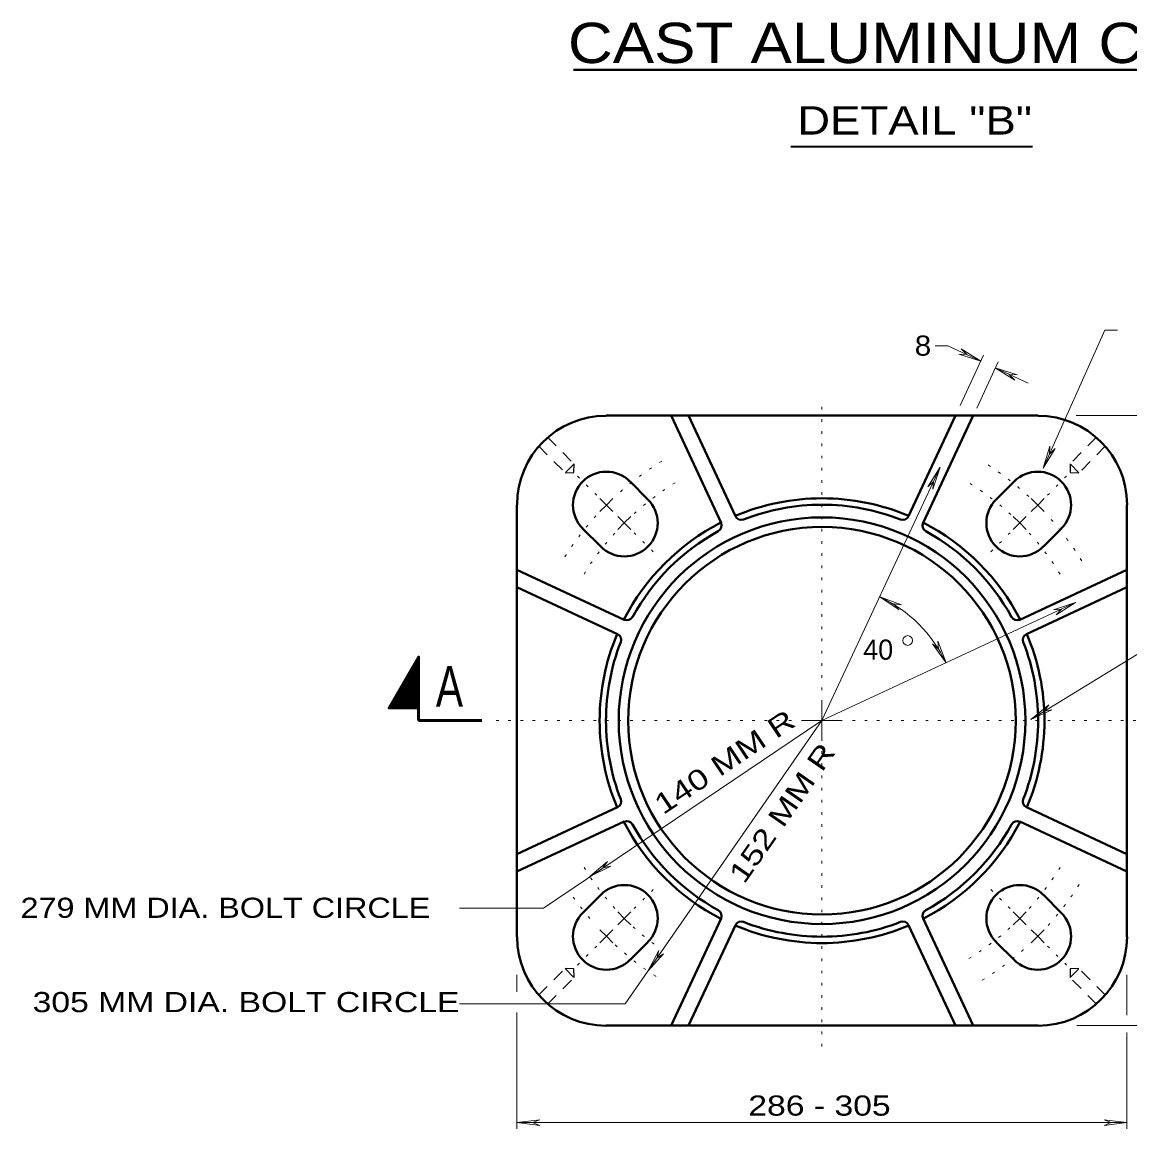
# Model space of a CAD drawing. Extents: x 312583 to 312854, y 144419 to 144597.
# Drawn here: x 312694.63 to 312736.4, y 144504.87 to 144546.6 of the extents above; entities that cross this region are included whole.
import ezdxf
from ezdxf.enums import TextEntityAlignment as Align

# ---------------------------------------------------------------- set-up
doc = ezdxf.new("R2010")
doc.units = 0
doc.header["$LTSCALE"] = 0.3
doc.linetypes.add('DOTTED', pattern=[1.5, 0.3, -1.2])
doc.linetypes.add('SHORT_DASHED', pattern=[2.7, 1.5, -1.2])
doc.layers.add('1', color=7, linetype='Continuous', lineweight=40)
doc.layers.add('2', color=7, linetype='Continuous', lineweight=13)

msp = doc.modelspace()

# ---------------------------------------------------------------- linework, layer by layer
at = {"layer": '1'}
for p, q in [((312724.7891, 144531.7639), (312716.6471, 144531.7639)), ((312720.9864, 144527.7159), (312719.1004, 144531.7639)), ((312721.5307, 144527.9689), (312719.7597, 144531.7639)), ((312732.9387, 144531.7639), (312724.7891, 144531.7639)), ((312728.0551, 144527.9689), (312729.8261, 144531.7639)), ((312728.5994, 144527.7159), (312730.4854, 144531.7639)), ((312717.5517, 144529.2799), (312718.2264, 144528.6052)), ((312731.3594, 144528.6052), (312732.0341, 144529.2799)), ((312713.2891, 144528.4059), (312713.2891, 144520.2639)), ((312736.2891, 144520.2639), (312736.2891, 144528.4059)), ((312716.4477, 144526.8265), (312715.7731, 144527.5012)), ((312733.8127, 144527.5012), (312733.1381, 144526.8265)), ((312717.3371, 144524.0665), (312713.2891, 144525.9525)), ((312732.2487, 144524.0665), (312736.2891, 144525.9525)), ((312717.0841, 144523.5222), (312713.2891, 144525.2932)), ((312732.5017, 144523.5222), (312736.2891, 144525.2932)), ((312713.2891, 144520.2639), (312713.2891, 144512.1142)), ((312736.2891, 144512.1142), (312736.2891, 144520.2639)), ((312717.0841, 144516.9979), (312713.2891, 144515.2269)), ((312732.5017, 144516.9979), (312736.2891, 144515.2269)), ((312717.3371, 144516.4535), (312713.2891, 144514.5675)), ((312732.2487, 144516.4535), (312736.2891, 144514.5675)), ((312715.7731, 144513.0189), (312716.4477, 144513.6935)), ((312733.1381, 144513.6935), (312733.8127, 144513.0189)), ((312720.9864, 144512.8042), (312719.1004, 144508.7639)), ((312728.5994, 144512.8042), (312730.4854, 144508.7639)), ((312721.5307, 144512.5512), (312719.7597, 144508.7639)), ((312728.0551, 144512.5512), (312729.8261, 144508.7639)), ((312718.2264, 144511.9149), (312717.5517, 144511.2402)), ((312732.0341, 144511.2402), (312731.3594, 144511.9149)), ((312716.6471, 144508.7639), (312724.7891, 144508.7639)), ((312724.7891, 144508.7639), (312732.9387, 144508.7639))]:
    msp.add_line(p, q, dxfattribs=at)
at = {"layer": '1', "linetype": 'SHORT_DASHED', "lineweight": 25}
for p, q in [((312714.4467, 144530.9435), (312715.4434, 144529.9469)), ((312735.1314, 144530.9435), (312734.1424, 144529.9469)), ((312714.1094, 144530.6062), (312715.1061, 144529.6095)), ((312735.4687, 144530.6062), (312734.4797, 144529.6095)), ((312714.1094, 144509.9215), (312715.1061, 144510.9105)), ((312735.4687, 144509.9215), (312734.4797, 144510.9105)), ((312714.4467, 144509.5842), (312715.4434, 144510.5732)), ((312735.1314, 144509.5842), (312734.1424, 144510.5732))]:
    msp.add_line(p, q, dxfattribs=at)
for points in [[(312715.4434, 144529.9469), (312715.1061, 144529.6095), (312715.4357, 144529.6172)], [(312734.4797, 144529.6095), (312734.1424, 144529.9469), (312734.1501, 144529.6172)], [(312715.1061, 144510.9105), (312715.4434, 144510.5732), (312715.4357, 144510.9029)], [(312734.1424, 144510.5732), (312734.4797, 144510.9105), (312734.1501, 144510.9029)]]:
    msp.add_lwpolyline(points, close=True, dxfattribs=at)
at = {"layer": '1'}
for centre, radius, start, end in [((312716.6451, 144528.4059), 3.3542, 90, 180), ((312732.9368, 144528.4059), 3.3542, 0, 90), ((312716.6586, 144528.3924), 1.2578, 45, 225), ((312732.9234, 144528.3924), 1.2578, 315, 135), ((312724.791, 144520.26), 8.3854, 90, 112.94673), ((312724.791, 144520.26), 8.3854, 67.05327, 90), ((312717.3371, 144527.714), 1.2578, 225, 45), ((312724.791, 144520.26), 8.1458, 90, 111.30566), ((312724.791, 144520.26), 8.1458, 68.69434, 90), ((312732.2449, 144527.714), 1.2578, 135, 315), ((312724.791, 144520.26), 7.6667, 90, 180), ((312721.744, 144528.0723), 0.2396, 205.00333, 291.30722), ((312724.791, 144520.26), 7.6667, 0, 90), ((312727.838, 144528.0723), 0.2396, 248.69278, 334.99667), ((312724.791, 144520.26), 8.3854, 117.05705, 152.95096), ((312724.791, 144520.26), 7.3073, 90, 180), ((312724.791, 144520.26), 8.1458, 118.68793, 151.31207), ((312720.7656, 144527.6161), 0.2396, 298.68804, 25.01264), ((312724.791, 144520.26), 7.3073, 0, 90), ((312728.8163, 144527.6161), 0.2396, 154.98736, 241.31196), ((312724.791, 144520.26), 8.3854, 27.05705, 62.95096), ((312724.791, 144520.26), 8.1458, 28.68793, 61.31207), ((312717.4349, 144524.2854), 0.2396, 244.98736, 331.31196), ((312732.1471, 144524.2854), 0.2396, 208.68804, 295.01264), ((312724.791, 144520.26), 8.3854, 157.05327, 180), ((312724.791, 144520.26), 8.1458, 158.69434, 180), ((312716.9787, 144523.307), 0.2396, 338.69278, 64.99667), ((312732.6032, 144523.307), 0.2396, 115.00333, 201.30722), ((312724.791, 144520.26), 8.1458, 0, 21.30566), ((312724.791, 144520.26), 8.3854, 0, 22.94673), ((312724.791, 144520.26), 8.3854, 180, 202.94673), ((312724.791, 144520.26), 8.1458, 180, 201.30566), ((312724.791, 144520.26), 7.6667, 180, 270), ((312724.791, 144520.26), 7.3073, 180, 270), ((312724.791, 144520.26), 7.6667, 270, 0), ((312724.791, 144520.26), 7.3073, 270, 0), ((312724.791, 144520.26), 8.1458, 338.69434, 0), ((312724.791, 144520.26), 8.3854, 337.05327, 0), ((312716.9787, 144517.213), 0.2396, 295.00333, 21.30722), ((312732.6032, 144517.213), 0.2396, 158.69278, 244.99667), ((312724.791, 144520.26), 8.3854, 207.05705, 242.95096), ((312717.4349, 144516.2347), 0.2396, 28.68804, 115.01264), ((312724.791, 144520.26), 8.1458, 208.68793, 241.31207), ((312724.791, 144520.26), 8.3854, 297.05705, 332.95096), ((312724.791, 144520.26), 8.1458, 298.68793, 331.31207), ((312732.1471, 144516.2347), 0.2396, 64.98736, 151.31196), ((312717.3371, 144512.8061), 1.2578, 315, 135), ((312732.2449, 144512.8061), 1.2578, 45, 225), ((312716.6586, 144512.1276), 1.2578, 135, 315), ((312720.7656, 144512.904), 0.2396, 334.98736, 61.31196), ((312728.8163, 144512.904), 0.2396, 118.68804, 205.01264), ((312732.9234, 144512.1276), 1.2578, 225, 45), ((312724.791, 144520.26), 8.3854, 247.05327, 270), ((312721.744, 144512.4478), 0.2396, 68.69278, 154.99667), ((312724.791, 144520.26), 8.1458, 248.69434, 270), ((312724.791, 144520.26), 8.1458, 270, 291.30566), ((312724.791, 144520.26), 8.3854, 270, 292.94673), ((312727.838, 144512.4478), 0.2396, 25.00333, 111.30722), ((312716.6451, 144512.1142), 3.3542, 180, 270), ((312732.9368, 144512.1142), 3.3542, 270, 0)]:
    msp.add_arc(centre, radius, start, end, dxfattribs=at)
at = {"layer": '1', "linetype": 'DOTTED', "lineweight": 13}
for radius, start, end in [(11.5, 121.67302, 132.67646), (11.5, 47.32354, 58.32698), (10.5417, 121.67021, 132.50277), (10.5417, 47.49723, 58.32979), (11.5, 137.83702, 148.35019), (11.5, 31.64981, 42.16298), (10.5417, 137.83921, 148.35431), (10.5417, 31.64569, 42.16079), (10.5417, 211.64569, 222.16079), (10.5417, 317.83921, 328.35431), (11.5, 317.83702, 328.35019), (11.5, 215.3347, 222.16255), (10.5417, 227.49787, 233.37708), (10.5417, 301.67021, 312.50277), (11.5, 227.32354, 238.32698), (11.5, 301.67302, 312.67646)]:
    msp.add_arc((312724.791, 144520.26), radius, start, end, dxfattribs=at)
at = {"layer": '2', "lineweight": 40}
msp.add_line((312715.4253, 144544.8043), (312740.0175, 144544.8043), dxfattribs=at)
at = {"layer": '2', "lineweight": 35}
for p, q in [((312723.6187, 144541.9064), (312732.7269, 144541.9064)), ((312709.5784, 144522.2495), (312709.4021, 144522.3492)), ((312709.5784, 144522.2802), (312709.4097, 144522.3722)), ((312709.5784, 144522.3109), (312709.4251, 144522.3952)), ((312709.5784, 144522.3339), (312709.4404, 144522.4105)), ((312709.5784, 144522.3645), (312709.4481, 144522.4335)), ((312709.5784, 144522.3875), (312709.4634, 144522.4565)), ((312709.5784, 144522.4105), (312709.4711, 144522.4795)), ((312709.5784, 144522.4412), (312709.4864, 144522.4949)), ((312709.5784, 144522.4719), (312709.4941, 144522.5179)), ((312709.5784, 144522.5025), (312709.5094, 144522.5409)), ((312709.5784, 144522.5255), (312709.5171, 144522.5562)), ((312709.5784, 144522.5562), (312709.5324, 144522.5792)), ((312709.5784, 144522.5792), (312709.5401, 144522.6022)), ((312709.5784, 144522.6099), (312709.5554, 144522.6175)), ((312709.5784, 144522.6405), (312709.5631, 144522.6405)), ((312709.5784, 144521.6975), (312709.1567, 144521.9352)), ((312709.5784, 144521.7205), (312709.1721, 144521.9582)), ((312709.5784, 144521.7512), (312709.1797, 144521.9812)), ((312709.5784, 144521.7819), (312709.1951, 144521.9965)), ((312709.5784, 144521.8125), (312709.2104, 144522.0195)), ((312709.5784, 144521.8355), (312709.2181, 144522.0425)), ((312709.5784, 144521.8662), (312709.2334, 144522.0579)), ((312709.5784, 144521.8892), (312709.2487, 144522.0809)), ((312709.5784, 144521.9199), (312709.2564, 144522.1039)), ((312709.5784, 144521.9429), (312709.2717, 144522.1192)), ((312709.5784, 144521.9735), (312709.2794, 144522.1422)), ((312709.5784, 144522.0042), (312709.2947, 144522.1652)), ((312709.5784, 144522.0272), (312709.3024, 144522.1805)), ((312709.5784, 144522.0579), (312709.3177, 144522.2112)), ((312709.5784, 144522.0809), (312709.3254, 144522.2265)), ((312709.5784, 144522.1115), (312709.3407, 144522.2495)), ((312709.5784, 144522.1422), (312709.3484, 144522.2725)), ((312709.5784, 144522.1652), (312709.3637, 144522.2879)), ((312709.5784, 144522.1959), (312709.3714, 144522.3109)), ((312709.5784, 144522.2189), (312709.3867, 144522.3339)), ((312709.5707, 144521.1455), (312708.9267, 144521.5212)), ((312709.5784, 144521.1762), (312708.9344, 144521.5442)), ((312709.5784, 144521.1992), (312708.9497, 144521.5595)), ((312709.5784, 144521.2222), (312708.9574, 144521.5825)), ((312709.5784, 144521.2529), (312708.9727, 144521.6055)), ((312709.5784, 144521.2835), (312708.9804, 144521.6209)), ((312709.5784, 144521.3142), (312708.9957, 144521.6439)), ((312709.5784, 144521.3372), (312709.0034, 144521.6669)), ((312709.5784, 144521.3679), (312709.0187, 144521.6822)), ((312709.5707, 144521.3909), (312709.0264, 144521.7129)), ((312709.5784, 144521.4215), (312709.0417, 144521.7282)), ((312709.5784, 144521.4445), (312709.0571, 144521.7512)), ((312709.5784, 144521.4752), (312709.0647, 144521.7742)), ((312709.5784, 144521.5059), (312709.0801, 144521.7895)), ((312709.5784, 144521.5289), (312709.0877, 144521.8125)), ((312709.5784, 144521.5595), (312709.1031, 144521.8355)), ((312709.5784, 144521.5902), (312709.1107, 144521.8509)), ((312709.5784, 144521.6132), (312709.1261, 144521.8739)), ((312709.5784, 144521.6439), (312709.1337, 144521.8969)), ((312709.5784, 144521.6745), (312709.1491, 144521.9122)), ((312709.3177, 144520.7392), (312708.6814, 144521.1072)), ((312709.3637, 144520.7392), (312708.6967, 144521.1225)), ((312709.4097, 144520.7392), (312708.7121, 144521.1455)), ((312709.4634, 144520.7392), (312708.7197, 144521.1685)), ((312709.5017, 144520.7392), (312708.7351, 144521.1839)), ((312709.5554, 144520.7392), (312708.7427, 144521.2145)), ((312709.5784, 144520.7545), (312708.7581, 144521.2299)), ((312709.5784, 144520.7852), (312708.7657, 144521.2529)), ((312709.5784, 144520.8159), (312708.7811, 144521.2759)), ((312709.5784, 144520.8389), (312708.7887, 144521.2912)), ((312709.5784, 144520.8695), (312708.8041, 144521.3142)), ((312709.5707, 144520.8925), (312708.8117, 144521.3372)), ((312709.5707, 144520.9232), (312708.8271, 144521.3525)), ((312709.5784, 144520.9462), (312708.8347, 144521.3755)), ((312709.5784, 144520.9769), (312708.8501, 144521.3985)), ((312709.5784, 144521.0075), (312708.8654, 144521.4139)), ((312709.5784, 144521.0305), (312708.8731, 144521.4369)), ((312709.5784, 144521.0612), (312708.8884, 144521.4599)), ((312709.5784, 144521.0919), (312708.9037, 144521.4829)), ((312709.5784, 144521.1149), (312708.9114, 144521.4982)), ((312708.4974, 144520.7392), (312708.4821, 144520.7545)), ((312708.5434, 144520.7392), (312708.4897, 144520.7775)), ((312708.5971, 144520.7392), (312708.5051, 144520.7929)), ((312708.6431, 144520.7392), (312708.5204, 144520.8159)), ((312708.6967, 144520.7392), (312708.5281, 144520.8389)), ((312708.7351, 144520.7392), (312708.5434, 144520.8542)), ((312708.7887, 144520.7392), (312708.5511, 144520.8772)), ((312708.8347, 144520.7392), (312708.5664, 144520.9002)), ((312708.8807, 144520.7392), (312708.5741, 144520.9155)), ((312708.9267, 144520.7392), (312708.5894, 144520.9462)), ((312708.9804, 144520.7392), (312708.5971, 144520.9615)), ((312709.0264, 144520.7392), (312708.6124, 144520.9845)), ((312709.0724, 144520.7392), (312708.6201, 144521.0075)), ((312709.1261, 144520.7392), (312708.6354, 144521.0229)), ((312709.1721, 144520.7392), (312708.6431, 144521.0459)), ((312709.2181, 144520.7392), (312708.6584, 144521.0612)), ((312709.2717, 144520.7392), (312708.6737, 144521.0842))]:
    msp.add_line(p, q, dxfattribs=at)
at = {"layer": '2'}
for p, q in [((312729.5347, 144534.3935), (312729.0517, 144534.3935)), ((312730.7844, 144533.8185), (312729.5347, 144534.3935)), ((312729.9487, 144534.0869), (312730.2477, 144534.0639)), ((312730.7844, 144533.8185), (312729.9487, 144534.0869)), ((312730.0407, 144534.2785), (312730.2477, 144534.0639)), ((312730.7844, 144533.8185), (312730.0407, 144534.2785)), ((312730.0024, 144532.1472), (312730.8841, 144534.0409)), ((312730.6234, 144532.0475), (312731.4284, 144533.7879)), ((312731.3134, 144533.5655), (312732.5631, 144532.9905)), ((312731.3134, 144533.5655), (312732.1491, 144533.2972)), ((312731.3134, 144533.5655), (312732.0571, 144533.1055)), ((312732.1491, 144533.2972), (312731.8501, 144533.3202)), ((312732.0571, 144533.1055), (312731.8501, 144533.3202)), ((312734.3724, 144531.7639), (312743.0587, 144531.7639)), ((312733.1304, 144529.7782), (312733.3834, 144530.6139)), ((312733.1304, 144529.7782), (312733.5827, 144530.5295)), ((312733.3834, 144530.6139), (312733.3681, 144530.3149)), ((312733.5827, 144530.5295), (312733.3681, 144530.3149)), ((312724.7891, 144520.2639), (312729.2434, 144529.8165)), ((312729.2434, 144529.8165), (312728.7747, 144529.0784)), ((312729.2434, 144529.8165), (312728.9708, 144528.9905)), ((312728.7747, 144529.0784), (312728.9928, 144529.2811)), ((312728.9708, 144528.9905), (312728.9928, 144529.2811)), ((312716.6624, 144528.3905), (312716.4171, 144528.6359)), ((312716.6624, 144528.3905), (312716.9001, 144528.6359)), ((312732.9234, 144528.3905), (312732.6781, 144528.6359)), ((312732.9234, 144528.3905), (312733.1687, 144528.6359)), ((312716.6624, 144528.3905), (312716.4171, 144528.1529)), ((312716.6624, 144528.3905), (312716.9001, 144528.1529)), ((312732.9234, 144528.3905), (312732.6781, 144528.1529)), ((312732.9234, 144528.3905), (312733.1687, 144528.1529)), ((312717.3371, 144527.7159), (312717.0917, 144527.9612)), ((312717.3371, 144527.7159), (312717.5824, 144527.9612)), ((312732.2487, 144527.7159), (312732.0034, 144527.9612)), ((312732.2487, 144527.7159), (312732.4864, 144527.9612)), ((312717.3371, 144527.7159), (312717.0917, 144527.4705)), ((312717.3371, 144527.7159), (312717.5824, 144527.4705)), ((312732.2487, 144527.7159), (312732.0034, 144527.4705)), ((312732.2487, 144527.7159), (312732.4864, 144527.4705)), ((312726.9664, 144524.9329), (312727.6947, 144524.4422)), ((312726.9664, 144524.9329), (312727.7867, 144524.6339)), ((312724.7891, 144520.2639), (312734.3494, 144524.7182)), ((312727.6947, 144524.4422), (312727.4954, 144524.6645)), ((312727.7867, 144524.6339), (312727.4954, 144524.6645)), ((312734.3494, 144524.7182), (312733.5186, 144524.4457)), ((312733.5186, 144524.4457), (312733.8158, 144524.4637)), ((312734.3494, 144524.7182), (312733.6143, 144524.2532)), ((312733.6143, 144524.2532), (312733.8158, 144524.4637)), ((312729.1514, 144523.2539), (312729.1821, 144522.9625)), ((312729.4657, 144522.4412), (312729.1514, 144523.2539)), ((312728.9597, 144523.1542), (312729.1821, 144522.9625)), ((312729.4657, 144522.4412), (312728.9597, 144523.1542)), ((312724.7891, 144520.2639), (312724.7891, 144521.0305)), ((312724.7891, 144520.2639), (312724.7891, 144521.0305)), ((312732.6627, 144520.3099), (312733.3451, 144520.8542)), ((312733.3451, 144520.8542), (312733.1687, 144520.6165)), ((312724.7891, 144520.2639), (312714.2857, 144513.1952)), ((312724.7891, 144520.2639), (312717.3677, 144509.5842)), ((312724.7891, 144520.2639), (312724.0224, 144520.2639)), ((312724.7891, 144520.2639), (312725.5557, 144520.2639)), ((312724.7891, 144520.2639), (312724.7891, 144519.4972)), ((312732.6627, 144520.3099), (312733.4601, 144520.6702)), ((312733.4601, 144520.6702), (312733.1687, 144520.6165)), ((312716.0414, 144514.3835), (312716.7007, 144514.9509)), ((312716.7007, 144514.9509), (312716.5321, 144514.7132)), ((312716.0414, 144514.3835), (312716.8234, 144514.7745)), ((312716.8234, 144514.7745), (312716.5321, 144514.7132)), ((312714.2857, 144513.1952), (312711.1271, 144513.1952)), ((312717.3371, 144512.8042), (312717.0917, 144513.0495)), ((312717.3371, 144512.8042), (312717.0917, 144513.0495)), ((312717.3371, 144512.8042), (312717.0917, 144512.5665)), ((312717.3371, 144512.8042), (312717.5824, 144513.0495)), ((312717.3371, 144512.8042), (312717.5824, 144512.5665)), ((312732.2487, 144512.8042), (312732.0034, 144513.0495)), ((312732.2487, 144512.8042), (312732.0034, 144512.5665)), ((312732.2487, 144512.8042), (312732.4864, 144513.0495)), ((312732.2487, 144512.8042), (312732.4864, 144512.5665)), ((312716.6624, 144512.1295), (312716.4171, 144512.3749)), ((312716.6624, 144512.1295), (312716.4171, 144512.3749)), ((312716.6624, 144512.1295), (312716.9001, 144512.3749)), ((312732.9234, 144512.1295), (312732.6781, 144512.3749)), ((312732.9234, 144512.1295), (312733.1687, 144512.3749)), ((312716.6624, 144512.1295), (312716.4171, 144511.8842)), ((312716.6624, 144512.1295), (312716.9001, 144511.8842)), ((312732.9234, 144512.1295), (312732.6781, 144511.8842)), ((312732.9234, 144512.1295), (312733.1687, 144511.8842)), ((312718.2264, 144510.8185), (312718.6327, 144511.5929)), ((312718.6327, 144511.5929), (312718.5637, 144511.3015)), ((312718.2264, 144510.8185), (312718.8091, 144511.4702)), ((312718.8091, 144511.4702), (312718.5637, 144511.3015)), ((312713.2891, 144510.6805), (312713.2891, 144510.0365)), ((312736.2891, 144510.6805), (312736.2891, 144509.1549)), ((312717.3677, 144509.5842), (312711.1271, 144509.5842)), ((312713.2891, 144509.2545), (312713.2891, 144504.8692)), ((312734.4031, 144508.7639), (312743.0587, 144508.7639)), ((312736.2891, 144508.5032), (312736.2891, 144504.8692)), ((312713.2891, 144505.1069), (312714.1554, 144505.2142)), ((312713.2891, 144505.1069), (312736.2891, 144505.1069)), ((312713.2891, 144505.1069), (312714.1554, 144504.9995)), ((312714.1554, 144505.2142), (312713.8794, 144505.1069)), ((312714.1554, 144504.9995), (312713.8794, 144505.1069)), ((312735.4227, 144505.2142), (312735.6987, 144505.1069)), ((312736.2891, 144505.1069), (312735.4227, 144505.2142)), ((312735.4227, 144504.9995), (312735.6987, 144505.1069)), ((312736.2891, 144505.1069), (312735.4227, 144504.9995))]:
    msp.add_line(p, q, dxfattribs=at)
at = {"layer": '2', "linetype": 'DOTTED'}
for p, q in [((312724.7891, 144521.4139), (312724.7891, 144532.4309)), ((312716.2944, 144528.7585), (312715.5201, 144529.5329)), ((312733.2914, 144528.7585), (312734.0581, 144529.5329)), ((312717.7051, 144527.3479), (312718.5714, 144526.4815)), ((312731.8807, 144527.3479), (312731.0144, 144526.4815)), ((312723.6391, 144520.2639), (312712.4151, 144520.2639)), ((312725.9391, 144520.2639), (312736.9484, 144520.2639)), ((312724.7891, 144519.1139), (312724.7891, 144507.9665)), ((312717.7051, 144513.1722), (312718.5714, 144514.0385)), ((312731.8807, 144513.1722), (312731.0144, 144514.0385)), ((312716.2944, 144511.7615), (312715.5201, 144510.9949)), ((312733.2914, 144511.7615), (312734.0581, 144510.9949))]:
    msp.add_line(p, q, dxfattribs=at)
at = {"layer": '2', "lineweight": 53}
for p in [(312709.5784, 144520.7392), (312711.9704, 144520.2639)]:
    msp.add_line(p, (312709.5784, 144520.2639), dxfattribs=at)
at = {"layer": '2'}
for points in [[(312733.1304, 144529.7782), (312735.4534, 144534.9915), (312735.9287, 144534.9915)], [(312732.6627, 144520.3099), (312744.3927, 144527.4782), (312744.8757, 144527.4782)]]:
    msp.add_lwpolyline(points, dxfattribs=at)
at = {"layer": '2', "lineweight": 53}
msp.add_lwpolyline([(312709.5784, 144520.7392), (312708.4667, 144520.7392), (312709.5784, 144522.6559)], close=True, dxfattribs=at)
at = {"layer": '2'}
msp.add_circle((312728.0225, 144523.2845), 0.1833, dxfattribs=at)
msp.add_arc((312724.791, 144520.26), 5.1536, 25.00431, 65.00757, dxfattribs=at)

# ---------------------------------------------------------------- texts
for s, height, width, p in [('CAST ALUMINUM CAP', 1.52, 1.15, (312727.6148, 144545.0587)), ('DETAIL "B"', 1.07, 1.2, (312728.2809, 144542.3618)), ('A', 1.533, 0.75, (312710.7437, 144520.7852))]:
    msp.add_text(s, height=height, dxfattribs=dict(at, width=width)).set_placement(p, align=Align.CENTER)
for s, width, p in [('8 ', 1.1, (312728.2864, 144534.0252)), ('279 MM DIA. BOLT CIRCLE', 1.2, (312694.5711, 144512.8255)), ('305 MM DIA. BOLT CIRCLE', 1.25, (312695.0266, 144509.2693)), ('286 - 305', 1.25, (312722.0103, 144505.3674))]:
    msp.add_text(s, height=0.76, dxfattribs=dict(at, width=width)).set_placement(p)
msp.add_text('40', height=0.76, dxfattribs=at).set_placement((312726.3429, 144522.5591))
at = {"layer": '2', "width": 1.3}
for s, rotation, p in [('140 MM R', 33.904, (312718.799, 144516.6922)), ('152 MM R', 55.183, (312721.8562, 144514.0691))]:
    msp.add_text(s, height=0.76, rotation=rotation, dxfattribs=at).set_placement(p)

doc.saveas('drawing.dxf')
